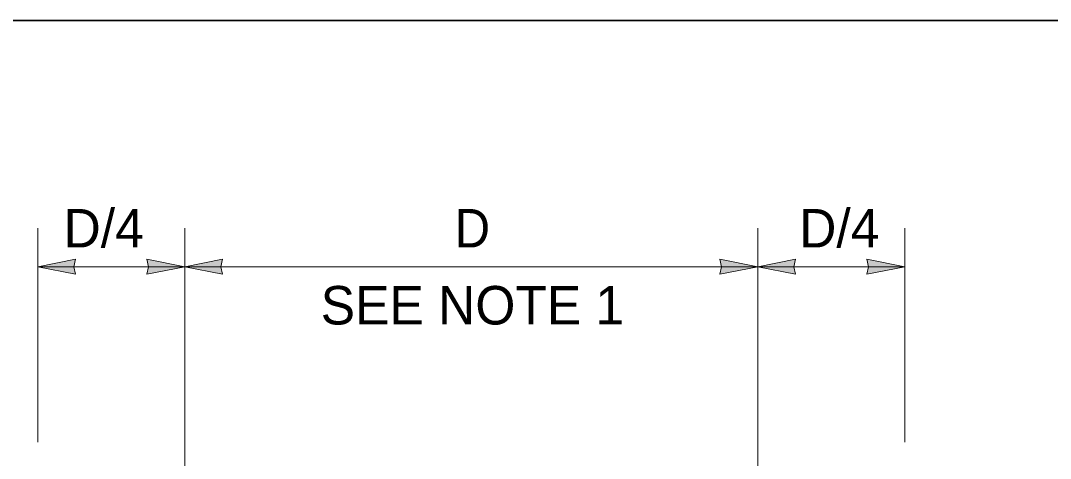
# Model space of a CAD drawing. Extents: x 99860 to 103153, y 99998 to 102077.
# Drawn here: x 100148 to 100575.7, y 101893.6 to 102075.5 of the extents above; entities that cross this region are included whole.
import ezdxf
from ezdxf.enums import TextEntityAlignment as Align

# ---------------------------------------------------------------- set-up
doc = ezdxf.new("R2010")
doc.units = 0
doc.header["$LTSCALE"] = 6.4
for name, color, linetype, lineweight in [('1', 7, 'Continuous', 13), ('15', 7, 'Continuous', 13), ('20', 7, 'Continuous', 13)]:
    doc.layers.add(name, color=color, linetype=linetype, lineweight=lineweight)

msp = doc.modelspace()

# ---------------------------------------------------------------- hatches: boundary and pattern name
at = {"layer": '15'}
for points in [[(100155.171, 101973.224), (100170.896, 101970.14), (100170.168, 101973.224), (100170.896, 101976.308)], [(100216.171, 101973.224), (100200.446, 101970.14), (100201.174, 101973.224), (100200.446, 101976.308)], [(100216.171, 101973.224), (100231.896, 101970.14), (100231.168, 101973.224), (100231.896, 101976.308)], [(100454.125, 101973.224), (100438.4, 101970.14), (100439.128, 101973.224), (100438.4, 101976.308)], [(100454.125, 101973.224), (100469.85, 101970.14), (100469.122, 101973.224), (100469.85, 101976.308)], [(100515.171, 101973.224), (100499.446, 101970.14), (100500.174, 101973.224), (100499.446, 101976.308)]]:
    msp.add_hatch(color=256, dxfattribs=at).paths.add_polyline_path(points)

# ---------------------------------------------------------------- linework, layer by layer
at = {"layer": '1', "lineweight": 35}
msp.add_lwpolyline([(99862, 99999.5), (103151, 99999.5), (103151, 102075.5), (99862, 102075.5)], close=True, dxfattribs=at)
at = {"layer": '15'}
for p, q in [((100155.171, 101900.289), (100155.171, 101989.224)), ((100216.171, 101765.803), (100216.171, 101989.224)), ((100454.125, 101765.803), (100454.125, 101989.224)), ((100515.171, 101900.289), (100515.171, 101989.224)), ((100155.171, 101973.224), (100216.171, 101973.224)), ((100216.171, 101973.224), (100454.125, 101973.224)), ((100454.125, 101973.224), (100515.171, 101973.224))]:
    msp.add_line(p, q, dxfattribs=at)
for points in [[(100155.171, 101973.224), (100170.896, 101970.14), (100170.168, 101973.224), (100170.896, 101976.308)], [(100216.171, 101973.224), (100200.446, 101970.14), (100201.174, 101973.224), (100200.446, 101976.308)], [(100216.171, 101973.224), (100231.896, 101970.14), (100231.168, 101973.224), (100231.896, 101976.308)], [(100454.125, 101973.224), (100438.4, 101970.14), (100439.128, 101973.224), (100438.4, 101976.308)], [(100454.125, 101973.224), (100469.85, 101970.14), (100469.122, 101973.224), (100469.85, 101976.308)], [(100515.171, 101973.224), (100499.446, 101970.14), (100500.174, 101973.224), (100499.446, 101976.308)]]:
    msp.add_lwpolyline(points, close=True, dxfattribs=at)

# ---------------------------------------------------------------- texts
at = {"layer": '20'}
for s, p in [('D/4', (100182.528, 101981.224)), ('D/4', (100487.998, 101981.224)), ('SEE NOTE 1', (100335.668, 101949.224))]:
    msp.add_text(s, height=16, dxfattribs=at).set_placement(p, align=Align.CENTER)
at = {"layer": '20', "width": 0.95}
msp.add_text('D', height=16, dxfattribs=at).set_placement((100335.668, 101981.224), align=Align.CENTER)

doc.saveas('drawing.dxf')
